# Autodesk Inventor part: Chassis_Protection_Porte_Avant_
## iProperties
Created: 2008-12
Part Number: Chassis_Protection_Porte_Avant_
Document SubType Name: Modeling
Designer: claivier
Author: claivier
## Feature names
1. Extrusion1
